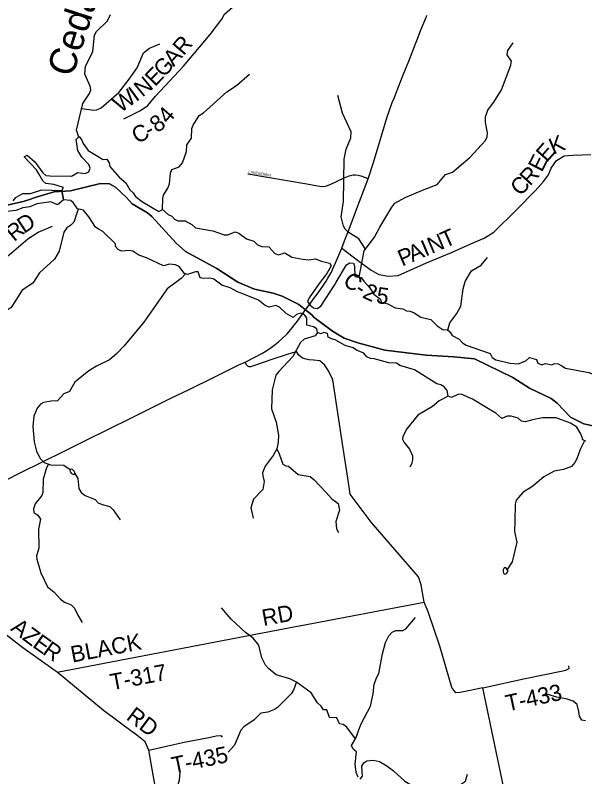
# Model space of a CAD drawing. Extents: x 1525783 to 1900577, y 218250 to 627376.
# Drawn here: x 1703033 to 1713510, y 457419 to 471414 of the extents above; entities that cross this region are included whole.
import ezdxf

# ---------------------------------------------------------------- set-up
doc = ezdxf.new("R2010")
doc.units = 0
for name, color, linetype in [('GM_X_County_Road', 7, 'Continuous'), ('GM_X_County_Road_Text', 7, 'Continuous'), ('GM_X_Major_Lake', 7, 'Continuous'), ('GM_X_Major_River', 7, 'Continuous'), ('GM_X_Minor_Lake', 7, 'Continuous'), ('GM_X_Minor_River', 7, 'Continuous'), ('GM_X_Minor_River_Text', 7, 'Continuous'), ('GM_X_State_Route', 7, 'Continuous'), ('GM_X_Township', 7, 'Continuous'), ('GM_X_Township_Road', 7, 'Continuous'), ('GM_X_Township_Road_Text', 7, 'Continuous'), ('GM_X_Township_Subdivision', 7, 'Continuous'), ('GM_X_Township_Subdivision_Text', 7, 'Continuous')]:
    doc.layers.add(name, color=color, linetype=linetype)

msp = doc.modelspace()

# ---------------------------------------------------------------- linework, layer by layer
at = {"layer": 'GM_X_County_Road'}
for points in [[(1705031, 469508), (1705153, 469570), (1705337, 469662), (1705470, 469757), (1705616, 469926), (1706129, 470477), (1706619, 471059), (1706733, 471211), (1706832, 471339), (1706883, 471432), (1707222, 471731), (1708015, 472395), (1708719, 472989), (1709218, 473366), (1709887, 473949), (1710428, 474403), (1711279, 475048), (1711317, 475077), (1711369, 475100)], [(1709555, 466748), (1709578, 466731), (1709591, 466721), (1709720, 466650), (1709897, 466618), (1710080, 466632), (1710596, 466863), (1711058, 467053), (1711469, 467236), (1711661, 467320), (1711840, 467428), (1712246, 467834), (1712603, 468191), (1712751, 468356), (1712842, 468484), (1712889, 468605), (1712991, 468747), (1713129, 468832), (1713293, 468842), (1713624, 468857)], [(1701713, 462128), (1701607, 462325), (1701324, 462820), (1701160, 463098), (1701099, 463314), (1700667, 465108), (1700661, 465509), (1700719, 465596), (1701429, 465928), (1701875, 466188), (1702226, 466449), (1702967, 467047), (1703264, 467304), (1703454, 467430), (1703719, 467539)], [(1709042, 467135), (1709355, 466897), (1709555, 466748)]]:
    msp.add_lwpolyline(points, dxfattribs=at)
at = {"layer": 'GM_X_Major_Lake'}
msp.add_line((1703924, 468022), (1703892, 468195), dxfattribs=at)
for points in [[(1703669, 468464), (1704066, 468455), (1704182, 468522), (1704320, 468503), (1704387, 468534), (1704410, 468606), (1704389, 468672), (1704260, 468806), (1704184, 468931), (1704152, 469132), (1704211, 469183), (1704261, 469121), (1704280, 469054), (1704374, 468931), (1704587, 468802), (1704647, 468761), (1704717, 468770), (1704758, 468704), (1704773, 468637), (1704945, 468437), (1705066, 468337), (1705144, 468204), (1705204, 468149), (1705247, 468081), (1705376, 467987), (1705676, 467807), (1705741, 467844), (1705844, 467749), (1705911, 467720), (1705963, 467665), (1706027, 467634), (1706157, 467637), (1706284, 467567), (1706350, 467510), (1706670, 467450), (1706879, 467381), (1706945, 467381), (1707078, 467433), (1707146, 467408), (1707289, 467306), (1707423, 467260), (1707488, 467193), (1707570, 467166), (1707700, 467157), (1707811, 467037), (1707878, 467012), (1707995, 467047), (1708120, 466969), (1708258, 466943), (1708326, 466932), (1708436, 466919), (1708557, 466937), (1708668, 466892), (1708812, 466860), (1708842, 466809), (1708763, 466670), (1708624, 466481), (1708438, 466221), (1708407, 466151), (1708456, 466083), (1708522, 466036), (1708588, 466027), (1708657, 466068), (1708907, 466454), (1708939, 466509), (1709126, 466830), (1709189, 466861), (1709255, 466856), (1709272, 466804), (1709278, 466613), (1709398, 466592), (1709445, 466525), (1709551, 466411), (1709630, 466288), (1709751, 466196), (1709764, 466140), (1709888, 466110), (1710025, 466034), (1710165, 466020), (1710230, 465983), (1710300, 465974), (1710370, 465945), (1710495, 465867), (1710681, 465823), (1710795, 465703), (1710906, 465635), (1710977, 465638), (1711028, 465594), (1711069, 465527), (1711200, 465461), (1711262, 465392), (1711327, 465353), (1711772, 465196), (1711807, 465126), (1711872, 465083), (1712139, 465017), (1712282, 465009), (1712425, 465063), (1712493, 465122), (1712621, 465089), (1712648, 465020)], [(1703892, 468195), (1703921, 468247), (1703741, 468303), (1703599, 468321), (1703542, 468369), (1703467, 468497), (1703422, 468571), (1703199, 468812), (1703251, 468840), (1703394, 468720), (1703542, 468518), (1703599, 468469), (1703669, 468464)], [(1713475, 463609), (1713454, 463674), (1713439, 463724), (1713365, 463842), (1713250, 463916), (1712981, 464016), (1712730, 464016), (1712612, 463991), (1712546, 463978), (1712417, 463942), (1712349, 463953), (1712282, 464008), (1712154, 464046), (1712084, 464046), (1711983, 464005), (1711874, 464101), (1711708, 464196), (1711444, 464360), (1711239, 464451), (1711175, 464444), (1711060, 464386), (1710996, 464415), (1710979, 464517), (1710926, 464582), (1710861, 464619), (1710791, 464640), (1710378, 464897), (1710111, 464977), (1710046, 465018), (1709904, 465026), (1709636, 465102), (1709568, 465106), (1709500, 465135), (1709443, 465202), (1709314, 465258), (1709251, 465303), (1709103, 465347), (1708918, 465450), (1708852, 465467), (1708789, 465500), (1708780, 465566), (1708714, 465585), (1708647, 465556), (1708592, 465581), (1708581, 465649), (1708519, 465690), (1708397, 465718), (1708397, 465850), (1708352, 465911), (1708285, 465938), (1708210, 465915), (1708147, 465860), (1708018, 465932), (1707893, 466052), (1707826, 466077), (1707707, 466048), (1707629, 466082), (1707510, 466179), (1707249, 466281), (1707124, 466329), (1706989, 466405), (1706833, 466451), (1706686, 466562), (1706612, 466585), (1706496, 466576), (1706436, 466591), (1706400, 466698), (1706349, 466697), (1706273, 466672), (1706202, 466648), (1706146, 466669), (1706050, 466797), (1705982, 466830), (1705868, 466837), (1705759, 466807), (1705449, 466957), (1705305, 467003), (1705196, 467079), (1705130, 467092), (1704989, 467080), (1704927, 467106), (1704880, 467163), (1704879, 467213), (1704644, 467439), (1704578, 467476), (1704507, 467521), (1704387, 467711), (1704287, 467834), (1704181, 467854), (1704098, 467975), (1704047, 468010), (1703924, 468022)], [(1713475, 463609), (1713454, 463674), (1713439, 463724), (1713365, 463842), (1713250, 463916), (1712981, 464016), (1712730, 464016), (1712612, 463991), (1712546, 463978), (1712417, 463942), (1712349, 463953), (1712282, 464008), (1712154, 464046), (1712084, 464046), (1711983, 464005), (1711874, 464101), (1711708, 464196), (1711444, 464360), (1711239, 464451), (1711175, 464444), (1711060, 464386), (1710996, 464415), (1710979, 464517), (1710926, 464582), (1710861, 464619), (1710791, 464640), (1710378, 464897), (1710111, 464977), (1710046, 465018), (1709904, 465026), (1709636, 465102), (1709568, 465106), (1709500, 465135), (1709443, 465202), (1709314, 465258), (1709251, 465303), (1709103, 465347), (1708918, 465450), (1708852, 465467), (1708789, 465500), (1708780, 465566), (1708714, 465585), (1708647, 465556), (1708592, 465581), (1708581, 465649), (1708519, 465690), (1708397, 465718), (1708397, 465850), (1708352, 465911), (1708285, 465938), (1708210, 465915), (1708147, 465860), (1708018, 465932), (1707893, 466052), (1707826, 466077), (1707707, 466048), (1707629, 466082), (1707510, 466179), (1707249, 466281), (1707124, 466329), (1706989, 466405), (1706833, 466451), (1706686, 466562), (1706612, 466585), (1706496, 466576), (1706436, 466591), (1706400, 466698), (1706349, 466697), (1706273, 466672), (1706202, 466648), (1706146, 466669), (1706050, 466797), (1705982, 466830), (1705868, 466837), (1705759, 466807), (1705449, 466957), (1705305, 467003), (1705196, 467079), (1705130, 467092), (1704989, 467080), (1704927, 467106), (1704880, 467163), (1704879, 467213), (1704644, 467439), (1704578, 467476), (1704507, 467521), (1704387, 467711), (1704287, 467834), (1704181, 467854), (1704098, 467975), (1704047, 468010), (1703924, 468022)], [(1712648, 465020), (1712722, 464991), (1712790, 465014), (1712904, 464991), (1712955, 465016), (1713023, 465005), (1713088, 464970), (1713158, 464927), (1713587, 464847), (1713788, 464768), (1713971, 464675), (1714033, 464676), (1714091, 464679), (1714548, 464417), (1714792, 464213), (1715005, 463997), (1715174, 463828), (1715252, 463777), (1715318, 463760)], [(1712648, 465020), (1712722, 464991), (1712790, 465014), (1712904, 464991), (1712955, 465016), (1713023, 465005), (1713088, 464970), (1713158, 464927), (1713587, 464847), (1713788, 464768), (1713971, 464675), (1714033, 464676), (1714091, 464679), (1714548, 464417), (1714792, 464213), (1715005, 463997), (1715174, 463828), (1715252, 463777), (1715318, 463760)], [(1713529, 463585), (1713475, 463609)]]:
    msp.add_lwpolyline(points, dxfattribs=at)
at = {"layer": 'GM_X_Major_River'}
msp.add_line((1703892, 468195), (1703924, 468022), dxfattribs=at)
for points in [[(1702995, 468005), (1703042, 468065), (1703171, 468139), (1703312, 468138), (1703523, 468207), (1703892, 468195)], [(1703924, 468022), (1703813, 467927), (1703687, 467987), (1703428, 467946), (1703304, 467891), (1703170, 467875), (1703042, 467825), (1702878, 467807), (1702813, 467810), (1702640, 467862)], [(1703924, 468022), (1703813, 467927), (1703687, 467987), (1703428, 467946), (1703304, 467891), (1703170, 467875), (1703042, 467825), (1702878, 467807), (1702813, 467810), (1702640, 467862)]]:
    msp.add_lwpolyline(points, dxfattribs=at)
at = {"layer": 'GM_X_Minor_Lake'}
for points in [[(1704044, 463065), (1704038, 463049), (1704043, 463023), (1704071, 462992), (1704109, 462974), (1704127, 462982), (1704128, 463010), (1704116, 463036), (1704098, 463052), (1704088, 463064), (1704066, 463073)], [(1704066, 463073), (1704044, 463065)], [(1712094, 461207), (1712085, 461229), (1712071, 461245), (1712053, 461257), (1712029, 461258), (1712011, 461224), (1712006, 461196), (1712016, 461162), (1712035, 461143), (1712059, 461149), (1712071, 461155), (1712088, 461181)], [(1712088, 461181), (1712093, 461193), (1712094, 461207)]]:
    msp.add_lwpolyline(points, dxfattribs=at)
at = {"layer": 'GM_X_Minor_River'}
for points in [[(1704200, 469174), (1704161, 469302), (1704278, 469790), (1704401, 469975), (1704422, 470045), (1704409, 470109), (1704312, 470331), (1704328, 470471), (1704460, 470748), (1704493, 471050), (1704526, 471118), (1704731, 471309), (1704783, 471425)], [(1704257, 469702), (1704481, 469671), (1704537, 469674), (1704614, 469714), (1704939, 469992), (1705131, 470242), (1705276, 470447), (1705390, 470726), (1705504, 470807), (1705691, 470889)], [(1709363, 466598), (1709453, 467082), (1709639, 467334), (1709741, 467517), (1709959, 467887), (1710018, 467958), (1710208, 468062), (1710526, 468200), (1710792, 468305), (1710947, 468485), (1711076, 468527), (1711394, 468798), (1711687, 469114), (1711716, 469182), (1711723, 469254), (1711684, 469445), (1711682, 469545), (1711729, 469669), (1711778, 469736), (1711836, 469814), (1711981, 470044), (1712152, 470495), (1712161, 470569), (1712082, 470686), (1712097, 470768), (1712192, 470907)], [(1705741, 467844), (1705748, 468055), (1705761, 468107), (1705843, 468236), (1705870, 468318), (1705887, 468510), (1705916, 468580), (1706049, 468630), (1706112, 468699), (1706181, 468909), (1706187, 469031), (1706275, 469154), (1706281, 469331), (1706304, 469395), (1706419, 469569), (1706494, 469623), (1706551, 469670), (1706924, 470008), (1707102, 470122), (1707344, 470331)], [(1709478, 467116), (1709354, 467306), (1709159, 467426), (1709100, 467485), (1709070, 467540), (1709031, 467711), (1709071, 467991), (1709082, 468770), (1709120, 468950), (1709206, 469163), (1709213, 469273), (1709052, 469616), (1708968, 469936)], [(1704190, 467852), (1704111, 467614), (1704053, 467553), (1703983, 467508), (1703927, 467428), (1703839, 467077), (1703755, 466929), (1703482, 466682), (1703356, 466491), (1703163, 466362), (1702960, 466045), (1702773, 465918)], [(1710990, 465627), (1711028, 465760), (1711157, 465931), (1711233, 466068), (1711276, 466388), (1711312, 466520), (1711429, 466715), (1711605, 466823), (1711723, 466961)], [(1706163, 466663), (1706083, 466576), (1705831, 466389), (1705396, 465775), (1705034, 465339), (1704905, 465199), (1704769, 465080), (1704526, 464963), (1704386, 464879), (1704130, 464669), (1704029, 464498), (1703928, 464457), (1703813, 464325), (1703693, 464324), (1703554, 464300), (1703499, 464266), (1703438, 464195), (1703375, 464047), (1703358, 463855), (1703382, 463576), (1703410, 463452), (1703425, 463399), (1703497, 463262), (1703564, 463195), (1703684, 463154), (1703927, 463144), (1704044, 463065)], [(1708592, 465581), (1708549, 465523), (1708349, 465458), (1708282, 465401), (1708140, 465142), (1707885, 464865), (1707827, 464802), (1707759, 464532), (1707749, 464180), (1707832, 463934), (1707876, 463699), (1707872, 463567), (1707844, 463443), (1707778, 463323), (1707632, 463129), (1707580, 463004), (1707588, 462949), (1707612, 462845), (1707588, 462701), (1707414, 462519), (1707370, 462363), (1707409, 462170)], [(1710996, 464415), (1710832, 464327), (1710706, 464221), (1710441, 464066), (1710237, 463815), (1710163, 463675), (1710160, 463621), (1710187, 463561), (1710283, 463441), (1710339, 463318), (1710344, 463248), (1710327, 463174), (1710292, 463110)], [(1713507, 463595), (1713424, 463436), (1713363, 463262), (1713328, 463193), (1713267, 463123), (1713118, 463066), (1712947, 463034), (1712826, 462970), (1712755, 462929), (1712556, 462761), (1712372, 462642), (1712247, 462503), (1712232, 462431), (1712223, 462113), (1712218, 461928), (1712261, 461731), (1712173, 461368), (1712083, 461230)], [(1707844, 463443), (1707891, 463354), (1707954, 463165), (1708011, 463132), (1708063, 463127), (1708237, 462972), (1708459, 462939), (1708525, 462884), (1708749, 462650), (1708848, 462534), (1708971, 462440), (1709001, 462317), (1708931, 462110), (1708943, 461974), (1708980, 461905)], [(1703648, 463166), (1703607, 463098), (1703545, 462891), (1703543, 462642), (1703522, 462586), (1703400, 462437), (1703372, 462345), (1703377, 462275), (1703446, 462224), (1703497, 462153), (1703458, 461968), (1703467, 461623), (1703426, 461477), (1703429, 461417), (1703483, 461229), (1703506, 461167), (1703626, 460907), (1703751, 460813), (1703865, 460681), (1703941, 460626), (1704059, 460581), (1704122, 460520), (1704182, 460387), (1704262, 460252)], [(1704127, 462990), (1704182, 462901), (1704205, 462714), (1704248, 462643), (1704322, 462586), (1704505, 462516), (1704556, 462455), (1704630, 462420), (1704774, 462388), (1704835, 462327), (1704965, 462141)], [(1709291, 458118), (1709133, 458332), (1709064, 458381), (1709000, 458390), (1708947, 458503), (1708817, 458511), (1708767, 458646), (1708703, 458647), (1708658, 458716), (1708591, 458775), (1708480, 458959), (1708208, 459160), (1708083, 459218), (1707834, 459291), (1707693, 459406), (1707636, 459471), (1707570, 459604), (1707516, 459839), (1707410, 459967), (1707271, 460071), (1707008, 460313), (1706829, 460524)], [(1709339, 457411), (1709302, 457497), (1709286, 457648), (1709314, 457880), (1709251, 457929), (1709220, 457992), (1709298, 458131), (1709370, 458332), (1709401, 458402), (1709568, 458718), (1709620, 458942), (1709633, 459118), (1709685, 459252), (1709724, 459318), (1709792, 459677), (1709845, 459885), (1709905, 460011), (1709967, 460074), (1710035, 460107), (1710165, 460109), (1710218, 460140), (1710396, 460346)], [(1708205, 459161), (1708150, 459012), (1708107, 458943), (1707856, 458690), (1707805, 458654), (1707678, 458608), (1707552, 458586), (1707423, 458459), (1707247, 458341), (1707182, 458274), (1707069, 457999), (1706949, 457874)], [(1713526, 458444), (1713456, 458461), (1713413, 458532), (1713399, 458616), (1713371, 458745), (1713296, 458808), (1713166, 458854), (1712990, 458879), (1712835, 458932), (1712767, 458931)], [(1709377, 457374), (1709419, 457430), (1709412, 457612), (1709445, 457676), (1709504, 457711), (1709626, 457723), (1709734, 457698), (1709871, 457621), (1709994, 457527), (1710199, 457338), (1710320, 457266), (1710546, 457248), (1710811, 457140), (1710946, 457170), (1711131, 457213), (1711319, 457337), (1711353, 457469)], [(1705451, 456633), (1705461, 456686), (1705642, 456838), (1705771, 456982), (1705897, 457083), (1706010, 457222), (1706052, 457354), (1706066, 457496), (1706057, 457568)]]:
    msp.add_lwpolyline(points, dxfattribs=at)
at = {"layer": 'GM_X_State_Route'}
for points in [[(1709319, 467864), (1709526, 468405), (1709626, 468708), (1709711, 468995), (1709809, 469321), (1709852, 469470), (1709877, 469547), (1709912, 469654), (1709970, 469808), (1710002, 469887), (1710043, 469987), (1710172, 470320), (1710272, 470572), (1710502, 471155), (1710567, 471319), (1710592, 471378), (1710613, 471418)], [(1706899, 464864), (1707148, 464987), (1707260, 465041), (1707443, 465131), (1707570, 465199), (1707659, 465251), (1707742, 465307), (1707813, 465360), (1707875, 465411), (1707936, 465465), (1708034, 465562), (1708105, 465641), (1708217, 465786), (1708375, 466000), (1708635, 466355), (1708718, 466474), (1708751, 466524), (1708785, 466583), (1708819, 466642), (1708848, 466694), (1708876, 466751), (1708903, 466806), (1708932, 466873), (1708986, 467003), (1709042, 467135), (1709091, 467268), (1709173, 467485), (1709319, 467864)], [(1702613, 462747), (1703126, 463002), (1703545, 463210), (1703920, 463397), (1704327, 463597), (1704775, 463820), (1705133, 463997), (1705505, 464183), (1705897, 464375), (1706233, 464539), (1706679, 464757), (1706899, 464864)]]:
    msp.add_lwpolyline(points, dxfattribs=at)
at = {"layer": 'GM_X_Township'}
for points in [[(1713715, 463856), (1713495, 463906), (1713247, 464025), (1713000, 464286), (1712889, 464369), (1712491, 464563), (1712186, 464755), (1711484, 465100), (1711101, 465137), (1710592, 465164), (1709832, 465257), (1709333, 465396), (1709085, 465480), (1708869, 465606), (1708534, 465860), (1708490, 465910), (1708375, 466000), (1708251, 466097), (1707943, 466250), (1707781, 466307), (1707432, 466378), (1707130, 466509), (1706740, 466759), (1706166, 467072), (1705993, 467225), (1705545, 467718), (1705467, 467785), (1705187, 467951), (1705081, 468062), (1704878, 468254), (1704770, 468317), (1704601, 468324), (1704051, 468186), (1703750, 468166), (1703417, 468072), (1703275, 468021), (1703181, 467988), (1702887, 467922)], [(1702887, 467922), (1703181, 467988), (1703275, 468021), (1703417, 468072), (1703750, 468166), (1704051, 468186), (1704601, 468324), (1704770, 468317), (1704878, 468254), (1705081, 468062), (1705187, 467951), (1705467, 467785), (1705545, 467718), (1705993, 467225), (1706166, 467072), (1706740, 466759), (1707130, 466509), (1707432, 466378), (1707781, 466307), (1707943, 466250), (1708251, 466097), (1708375, 466000), (1708490, 465910), (1708534, 465860), (1708869, 465606), (1709085, 465480), (1709333, 465396), (1709832, 465257), (1710592, 465164), (1711101, 465137), (1711484, 465100), (1712186, 464755), (1712491, 464563), (1712889, 464369), (1713000, 464286), (1713247, 464025), (1713495, 463906), (1713715, 463856)]]:
    msp.add_lwpolyline(points, dxfattribs=at)
at = {"layer": 'GM_X_Township_Road'}
for points in [[(1708192, 465228), (1708036, 465178), (1707752, 465088), (1707433, 464978), (1707360, 464955), (1707336, 464955), (1707313, 464962), (1707297, 464976), (1707283, 464996), (1707260, 465041)], [(1709066, 463458), (1708875, 464714), (1708795, 464879), (1708723, 464988), (1708634, 465061), (1708520, 465075), (1708434, 465083), (1708383, 465094), (1708317, 465114), (1708248, 465167), (1708224, 465205), (1708205, 465232), (1708192, 465228)], [(1712155, 456567), (1711632, 459052), (1711372, 458998), (1711215, 458969), (1711139, 458959), (1711067, 459059), (1710846, 459818), (1710631, 460448), (1710555, 460626), (1710498, 460949), (1710452, 461094), (1709579, 462096), (1709195, 462614), (1709162, 462825), (1709071, 463422), (1709066, 463458)], [(1703767, 459367), (1703765, 459368), (1703172, 459787), (1702011, 460684), (1701268, 461269), (1701126, 461374)], [(1708287, 460196), (1708290, 460197), (1710555, 460626)], [(1703804, 459341), (1708287, 460196)], [(1705214, 458226), (1705211, 458228), (1704659, 458636), (1703804, 459341), (1703767, 459367)], [(1711632, 459052), (1712415, 459224), (1713075, 459358), (1713164, 459376), (1713225, 459408), (1713218, 459460)], [(1705887, 455638), (1705491, 457909), (1705426, 458059), (1705271, 458184), (1705214, 458226)], [(1705491, 457909), (1706140, 458052), (1706594, 458140), (1706731, 458173), (1706815, 458178), (1706841, 458147)]]:
    msp.add_lwpolyline(points, dxfattribs=at)
at = {"layer": 'GM_X_Township_Subdivision'}
msp.add_lwpolyline([(1707314, 468499), (1708399, 468317), (1708594, 468280), (1708680, 468265), (1708742, 468273), (1708828, 468301), (1708940, 468361), (1709085, 468424), (1709174, 468463), (1709248, 468483), (1709291, 468481), (1709341, 468475), (1709393, 468462), (1709476, 468429), (1709526, 468405)], dxfattribs=at)

# ---------------------------------------------------------------- texts
at = {"layer": 'GM_X_County_Road_Text'}
for s, rotation, p in [('R', 49.8792, (1706130, 470660)), ('A', 48.471, (1705949, 470457)), ('G', 47.0364, (1705764, 470257)), ('E', 45.8364, (1705603, 470091)), ('N', 39.341, (1705371, 469899)), ('I', 35.662, (1705255, 469814)), ('W', 35.3746, (1704970, 469612)), ('4', 48.5379, (1705847, 469400)), ('8', 36.0572, (1705645, 469243)), ('C', 26.778, (1705272, 469045)), ('-', 28.7525, (1705502, 469162)), ('K', 23.0326, (1712930, 468848)), ('E', 48.7238, (1712810, 468700)), ('E', 63.0163, (1712720, 468516)), ('R', 47.6976, (1712504, 468262)), ('C', 45.1628, (1712321, 468077)), ('D', 33.6486, (1703195, 467394)), ('R', 39.5742, (1703012, 467242)), ('T', 23.9337, (1710940, 467131)), ('N', 23.1524, (1710693, 467025)), ('A', 23.0592, (1710337, 466873)), ('I', 23.0622, (1710579, 466977)), ('P', 23.0588, (1710150, 466794)), ('C', 321.8662, (1709040, 466489)), ('2', 335.3713, (1709404, 466231)), ('-', 327.823, (1709262, 466317)), ('5', 351.7527, (1709662, 466127))]:
    msp.add_text(s, height=300, rotation=rotation, dxfattribs=at).set_placement(p)
at = {"layer": 'GM_X_Minor_River_Text'}
msp.add_text('Cedar', height=500.1, rotation=72.0151, dxfattribs=at).set_placement((1704083, 470258))
at = {"layer": 'GM_X_Township_Road_Text'}
for s, rotation, p in [('RD', 10.4372, (1707600, 460189)), ('A', 322.1992, (1702933, 460120)), ('Z', 323.457, (1703147, 459953)), ('E', 324.7694, (1703334, 459815)), ('BLACK', 10.8321, (1704083, 459516)), ('R', 325.0072, (1703518, 459685)), ('T-317', 10.7062, (1704809, 459007)), ('T-433', 12.0169, (1712088, 458619)), ('RD', 323.0337, (1705057, 458485)), ('T-435', 11.6889, (1705943, 457479))]:
    msp.add_text(s, height=300, rotation=rotation, dxfattribs=at).set_placement(p)
at = {"layer": 'GM_X_Township_Subdivision_Text'}
for s, rotation, p in [('LAKESIDE', 350.6784, (1707319, 468513)), ('DR', 351.0309, (1707636, 468460))]:
    msp.add_text(s, height=50, rotation=rotation, dxfattribs=at).set_placement(p)

doc.saveas('drawing.dxf')
